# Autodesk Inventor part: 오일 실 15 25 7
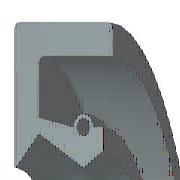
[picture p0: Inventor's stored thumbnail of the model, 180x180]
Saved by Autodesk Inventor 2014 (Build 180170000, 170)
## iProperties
Created: 2012-02
Part Number: 오일 실 15 25 7
Material: 고무
Description: 오일-실
Document SubType Name: Modeling
Standard: KS B 2804
Designer: mduedu
Standards Organization: KS
Language: ko-KR
Size Designation: D - 15 25 7
Categories: <MemberInstance><Categories><Category DisplayName="샤프트 부품" InternalName="7f7aeb1f-a693-4053-b835-cee3144e0d98" Mnemonic="SHFT"><Category DisplayName="실링" Intern
Density: 0.93 g/cm^3
Appearance: 고무 - 검은색 - 버전 1.1
IsCustomPart: 1
Author: mduedu
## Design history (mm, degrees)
revolve "본체" stored, may be unused: angle "d17" = 90 deg
revolve "스프링1" stored, may be unused: angle "d18" = 90 deg
body "Solid1"
sketch "스케치1"
  geometry: L1 (0, 12.5)-(7, 12.5); L2 (7, 10.75)-(1.75, 10.75); L3 (1.75, 9.25)-(4.9, 7.5); L4 (4.9, 7.5)-(0, 7.5); L5 (0, 0)-(9.586, 0) reference; L6 (4.9, 7.5)-(6.3, 8.375); L7 (0, 18)-(0, -3) reference; L8 (-1.941, 0)-(11.507, 0) reference; L9 (4.2, 9.6)-(1.75, 10.09); L10 (1.75, 10.09)-(1.75, 10.75); L11 (0, 12.5)-(0, 7.588); L12 (4.9, 7.5)-(0, 7.5); L13 (1.75, 9.25)-(0.152, 7.528); L14 (7, 12.5)-(7, 10.75); L15 (5.6, 9.6)-(6.3, 9.6); L16 (6.3, 9.6)-(6.3, 8.375); C1 r 0.455 at (4.9, 9.6); A1 r 0.7 centre (4.9, 9.6) between (5.6, 9.6) and (4.2, 9.6); A2 r 0.088 centre (0.088, 7.588) between (0, 7.588) and (0.152, 7.528); 1 further point
  constraints: 28 end point, 5 horizontal alignment, 5 point on line, 4 point on circle, 4 vertical alignment, 3 centre point, 3 tangent, 2 collinear, 2 horizontal, 2 perpendicular, 1 coincident, 1 parallel
  dimensions: "d0" = 25 diameter of L1 L5 (= SD2); "d1" = 1.75 distance of L1.end L2.start (= SD); "d2" = 0.91 diameter of C1 (= SPDI); "d3" = 1.4 diameter of A1 (= SPDA); "d4" = 15 diameter of L3.end L5 (= NND); "d5" = 18.5 diameter of L3.start L5 (= TKDM); "d7" = 20.18 diameter of L9.end L5 (= TKDM + 0.24 x SWDT); "d8" = 1.75 distance between parallel lines of L11 L10 (= SD); "d9" = 4.9 distance from line of L11 C1.centre (= SPDST); "d10" = 19.2 diameter of C1.centre L5 (= HLDM); "d11" = 0.0875 radius of A2 (= 0.25 x LAB); "d12" = 6.3 distance between parallel lines of L11 L16 (= SDI); "d13" = 16.75 diameter of L6.end L5 (= ABDM); "d14" = 7 distance from line of L11 L1.end (= SWDT)
fillet "모깎기1" dims "d6" = 0.3 (= RR)
other parameters: "SD2" = 25 [user parameter; used in 1 equation term], "SWDT" = 7 [user parameter; used in 2 equation terms], "RR" = 0.3 [user parameter; used in 1 equation term], "SD" = 1.75 [user parameter; used in 2 equation terms], "NND" = 15 [user parameter; used in 1 equation term], "SPDA" = 1.4 [user parameter; used in 1 equation term], "SPDI" = 0.91 [user parameter; used in 1 equation term], "TKDM" = 18.5 [user parameter; used in 2 equation terms], "HLDM" = 19.2 [user parameter; used in 1 equation term], "ABDM" = 16.75 [user parameter; used in 1 equation term], "SDI" = 6.3 [user parameter; used in 1 equation term], "SPDST" = 4.9 [user parameter; used in 1 equation term], "LAB" = 0.35 [user parameter; used in 1 equation term], "d15" = 0, "d16" = 0, "d19" = 0
